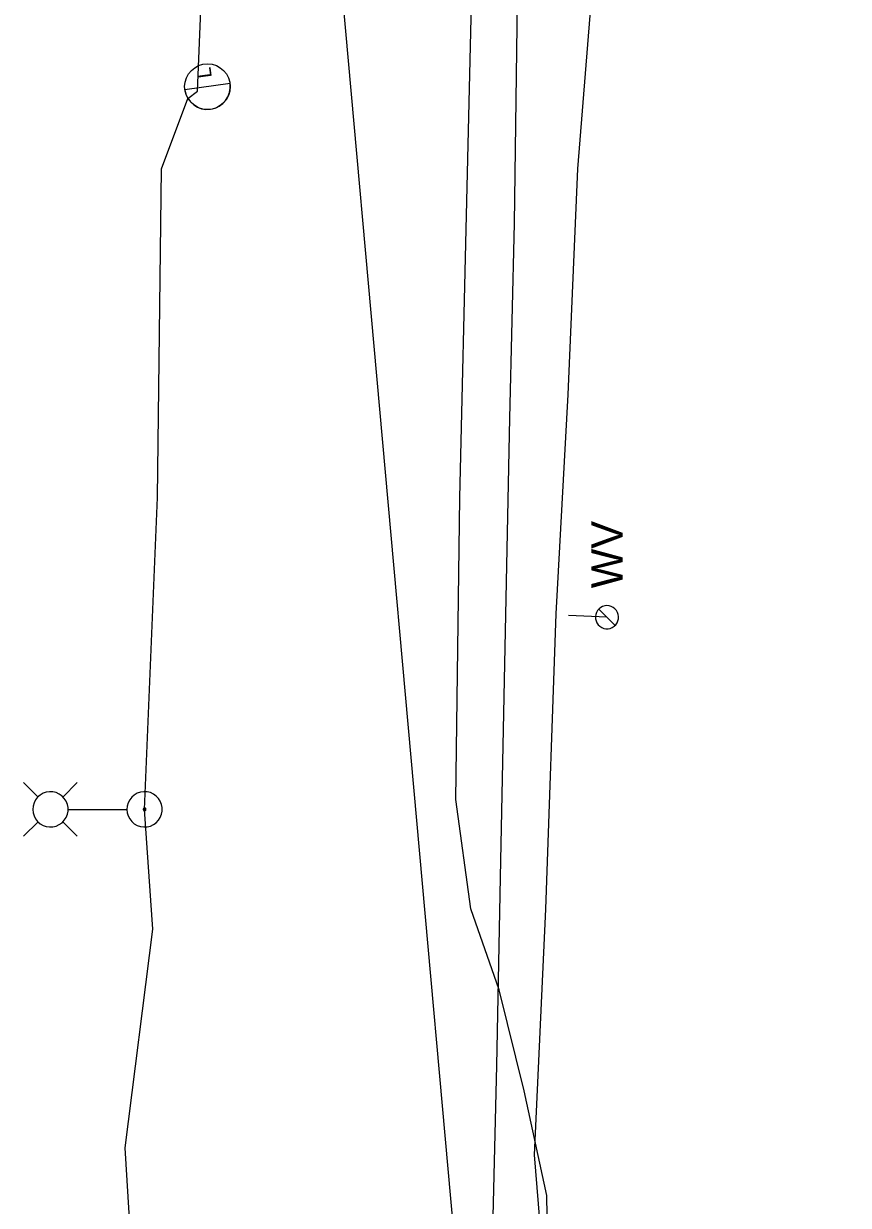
# Model space of a CAD drawing. Extents: x 596028 to 606371, y 330010 to 403088.
# Drawn here: x 604993.1 to 605094.7, y 333256.4 to 333402 of the extents above; entities that cross this region are included whole.
import ezdxf

# ---------------------------------------------------------------- set-up
doc = ezdxf.new("R2010")
doc.units = 0
for name, color, linetype in [('E_LTG', 7, 'Continuous'), ('E_LTG_CID', 7, 'Continuous'), ('E_UTL_G_UG', 7, 'Continuous'), ('E_UTL_SAN_UG', 7, 'Continuous'), ('E_UTL_TV_UG', 7, 'Continuous'), ('E_UTL_W', 7, 'Continuous'), ('E_UTL_W_UG', 7, 'Continuous')]:
    doc.layers.add(name, color=color, linetype=linetype)

# ---------------------------------------------------------------- blocks, each defined once
blk = doc.blocks.new('_U272')
at = {"layer": 'E_LTG'}
blk.add_lwpolyline([(0.0007, -0.171), (0.0007, 0.1718)], dxfattribs=at)
blk.add_circle((0.0007, 0.0004), 0.1714, dxfattribs=at)
blk.add_arc((0.0007, 0.0004), 0.1714, 90, 270, dxfattribs=at)
blk.add_text('L', height=0.108, dxfattribs=at).set_placement((0.066, -0.0422))

msp = doc.modelspace()

# ---------------------------------------------------------------- linework, layer by layer
at = {"layer": 'E_LTG'}
for points in [[(604994.83, 333306.74), (604993.05, 333308.52)], [(604997.87, 333306.74), (604999.65, 333308.52)], [(604994.18, 333305.22), (604994.22, 333304.81), (604994.33, 333304.41), (604994.52, 333304.04), (604994.78, 333303.72), (604995.09, 333303.45), (604995.45, 333303.24), (604995.84, 333303.11), (604996.25, 333303.05), (604996.66, 333303.07), (604997.06, 333303.16), (604997.44, 333303.34), (604997.78, 333303.58), (604998.06, 333303.88), (604998.29, 333304.22), (604998.44, 333304.61), (604998.52, 333305.01), (604998.52, 333305.43), (604998.44, 333305.83), (604998.29, 333306.22), (604998.06, 333306.57), (604997.78, 333306.86), (604997.44, 333307.1), (604997.06, 333307.28), (604996.66, 333307.37), (604996.25, 333307.39), (604995.84, 333307.33), (604995.45, 333307.2), (604995.09, 333306.99), (604994.78, 333306.72), (604994.52, 333306.4), (604994.33, 333306.03), (604994.22, 333305.63), (604994.18, 333305.22)], [(605005.78, 333305.22), (605005.82, 333304.81), (605005.94, 333304.41), (605006.13, 333304.04), (605006.38, 333303.72), (605006.69, 333303.45), (605007.05, 333303.24), (605007.44, 333303.11), (605007.85, 333303.05), (605008.27, 333303.07), (605008.67, 333303.16), (605009.04, 333303.34), (605009.38, 333303.58), (605009.67, 333303.88), (605009.89, 333304.22), (605010.04, 333304.61), (605010.12, 333305.01), (605010.12, 333305.43), (605010.04, 333305.83), (605009.89, 333306.22), (605009.67, 333306.57), (605009.38, 333306.86), (605009.04, 333307.1), (605008.67, 333307.28), (605008.27, 333307.37), (605007.85, 333307.39), (605007.44, 333307.33), (605007.05, 333307.2), (605006.69, 333306.99), (605006.38, 333306.72), (605006.13, 333306.4), (605005.94, 333306.03), (605005.82, 333305.63), (605005.78, 333305.22)], [(604998.56, 333305.22), (605005.74, 333305.22)], [(605007.79, 333305.22), (605007.79, 333305.19), (605007.8, 333305.16), (605007.82, 333305.13), (605007.84, 333305.11), (605007.86, 333305.08), (605007.89, 333305.07), (605007.92, 333305.06), (605007.95, 333305.05), (605007.98, 333305.06), (605008.01, 333305.06), (605008.04, 333305.08), (605008.06, 333305.09), (605008.09, 333305.12), (605008.1, 333305.14), (605008.12, 333305.17), (605008.12, 333305.2), (605008.12, 333305.24), (605008.12, 333305.27), (605008.1, 333305.3), (605008.09, 333305.32), (605008.06, 333305.35), (605008.04, 333305.36), (605008.01, 333305.38), (605007.98, 333305.39), (605007.95, 333305.39), (605007.92, 333305.38), (605007.89, 333305.37), (605007.86, 333305.36), (605007.84, 333305.34), (605007.82, 333305.31), (605007.8, 333305.28), (605007.79, 333305.25), (605007.79, 333305.22)], [(604994.83, 333303.69), (604993.05, 333301.92)], [(604997.87, 333303.69), (604999.65, 333301.92)]]:
    msp.add_lwpolyline(points, dxfattribs=at)
at = {"layer": 'E_LTG_CID'}
for points in [[(605014.47, 333393.69), (605015.31, 333413.75), (605015.88, 333465.08), (605016.33, 333493.73), (605016.6, 333495.89), (605016.64, 333498.09), (605017.72, 333545.18), (605018.86, 333593.18)], [(605007.96, 333305.22), (605009.56, 333343.65), (605010.05, 333384.12), (605013.28, 333392.8), (605014.47, 333393.69)], [(605004.43, 333142.5), (605005.3, 333147), (605005.59, 333179.13), (605007.26, 333236.01), (605005.55, 333263.51), (605008.97, 333290.48), (605007.96, 333305.22)]]:
    msp.add_lwpolyline(points, dxfattribs=at)
at = {"layer": 'E_UTL_G_UG'}
msp.add_lwpolyline([(605067.35, 332890.68), (605061.21, 332951.97), (605055.05, 333004.59), (605053.86, 333028.21), (605052.5, 333057.99), (605051.57, 333081.36), (605049.66, 333125.99), (605049.8, 333176.37), (605050.05, 333219.56), (605051.36, 333273.68), (605051.84, 333298.93), (605052.97, 333353.42), (605053.54, 333377.39), (605054.31, 333435.25), (605055.56, 333475.58), (605057.16, 333564.52), (605058.44, 333615), (605058.65, 333665.55), (605058.49, 333700.45), (605060.44, 333765.47), (605057.13, 333874.76), (605051.05, 333995.08)], dxfattribs=at)
at = {"layer": 'E_UTL_SAN_UG'}
msp.add_line((605061.78, 333078.09), (605028.59, 333447.6), dxfattribs=at)
at = {"layer": 'E_UTL_TV_UG'}
msp.add_lwpolyline([(605094.66, 332749.57), (605093.19, 332767.66), (605089.64, 332794.29), (605088.03, 332813.98), (605084.1, 332862.98), (605082.36, 332885.78), (605078.4, 332931.64), (605073.44, 332982.37), (605071.45, 333013.37), (605067.62, 333058.93), (605065.49, 333085.16), (605061.42, 333132.77), (605058.07, 333175.2), (605056.52, 333223.42), (605057.28, 333240.58), (605057.66, 333247.69), (605057.53, 333257.64), (605054.7, 333270.55), (605051.63, 333282.99), (605048.15, 333292.97), (605046.32, 333306.44), (605046.78, 333343.6), (605047.66, 333380.14), (605052.04, 333566.05)], dxfattribs=at)
at = {"layer": 'E_UTL_W'}
for points in [[(605064.92, 333330.32), (605064.65, 333330.29), (605064.39, 333330.22), (605064.15, 333330.09), (605063.94, 333329.92), (605063.76, 333329.72), (605063.62, 333329.48), (605063.54, 333329.23), (605063.5, 333328.96), (605063.51, 333328.69), (605063.57, 333328.43), (605063.69, 333328.18), (605063.84, 333327.96), (605064.04, 333327.77), (605064.27, 333327.62), (605064.52, 333327.52), (605064.79, 333327.47), (605065.06, 333327.47), (605065.32, 333327.52), (605065.57, 333327.62), (605065.8, 333327.77), (605066, 333327.96), (605066.16, 333328.18), (605066.27, 333328.43), (605066.33, 333328.69), (605066.35, 333328.96), (605066.31, 333329.23), (605066.22, 333329.48), (605066.08, 333329.72), (605065.91, 333329.92), (605065.69, 333330.09), (605065.45, 333330.22), (605065.19, 333330.29), (605064.92, 333330.32)], [(605065.93, 333327.88), (605063.91, 333329.9)]]:
    msp.add_lwpolyline(points, dxfattribs=at)
at = {"layer": 'E_UTL_W_UG'}
for points in [[(605059.31, 333221.93), (605056, 333262.67), (605057.38, 333292.93), (605058.68, 333329.31), (605060.15, 333356.33), (605061.34, 333384.12), (605063.5, 333411.21), (605065.77, 333449.13), (605067.83, 333478.45)], [(605064.92, 333328.89), (605060.2, 333329.12)]]:
    msp.add_lwpolyline(points, dxfattribs=at)

# ---------------------------------------------------------------- block references
at = {"layer": 'E_LTG_CID', "xscale": 16.404166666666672, "yscale": 16.404166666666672, "rotation": 97.82095686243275}
msp.add_blockref('_U272', (605015.71, 333394.24), dxfattribs=at)

# ---------------------------------------------------------------- texts
at = {"layer": 'E_UTL_W'}
msp.add_text('WV', height=3.85, rotation=90, dxfattribs=at).set_placement((605066.85, 333332.46))

doc.saveas('drawing.dxf')
